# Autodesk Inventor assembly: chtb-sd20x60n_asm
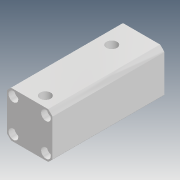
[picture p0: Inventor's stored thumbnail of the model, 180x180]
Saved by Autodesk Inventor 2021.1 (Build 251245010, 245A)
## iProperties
Company: Microsoft
Created: 2018-04
Part Number: chtb-sd20x60n_asm
Description: STEP AP214
Document SubType Name: Assembly
Designer: user
Title: chtb-sd20x60n_asm.STEP
Author: Windows
Revision Number: ÈÎºÎ
Sending System: SolidWorks 2015
Preprocessor: SwSTEP 2.0
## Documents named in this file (4)
- D:\Vault_2016\Projekty\Clamptek\Hydraulic\CHTB\CHTB-20\Inventor\CHTB-SD20x60N\chtb-sd20x60n_asm.iam
- D:\Vault_2016\Projekty\Clamptek\Hydraulic\CHTB\CHTB-20\Inventor\CHTB-SD20x60N\CHTB-SD20X60NBT.ipt
- D:\Vault_2016\Projekty\Clamptek\Hydraulic\CHTB\CHTB-20\Inventor\CHTB-SD20x60N\CHTB-SD20X60NHSG.ipt
- D:\Vault_2016\Projekty\Clamptek\Hydraulic\CHTB\CHTB-20\Inventor\CHTB-SD20x60N\QG.ipt
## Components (3 placed, 3 different names)
1. CHTB-SD20X60NBT_1
2. CHTB-SD20X60NHSG_2
3. QG_3
